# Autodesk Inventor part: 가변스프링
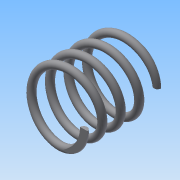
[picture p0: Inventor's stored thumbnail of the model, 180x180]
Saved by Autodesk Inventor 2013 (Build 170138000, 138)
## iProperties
Created: 2017-07
Part Number: 가변스프링
Material: 일반
Document SubType Name: Modeling
Designer: Administrator
Density: 1 g/cm^3
Author: Administrator
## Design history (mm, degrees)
sketch "스케치1"
  geometry: L1 (8.5, 0)-(0, 0); L2 (0, 0)-(0, 20.5); L3 (0, 20.5)-(8.5, 20.5); C1 r 1 at (8.5, 0)
  constraints: 6 end point, 1 centre point, 1 horizontal, 1 horizontal alignment, 1 parallel, 1 perpendicular
  dimensions: "d0" = 2 diameter of C1; "d1" = 8.5 distance of L1.start L1.end; "d2" = 8.5 distance of L2.end L3.end; "d3" = 20.5 distance of L1.end L2.end (derived)
feature "코일2" sketch "스케치1" pitch "d17" = 10; turns "d19" = 4; dims "d18" = 20.5 (= d3), "d20" = 0, angle "d21" = 90 deg, angle "d22" = 90 deg, "d23" = 0, "d24" = 0
sketch "스케치3"
  geometry: L1 (0, 15)-(20.5, 15); L2 (20.5, 15)-(20.5, -15); L3 (20.5, -15)-(0, -15); L4 (0, -15)-(0, 15); 2 further points
  constraints: 8 end point, 2 parallel, 1 coincident, 1 horizontal, 1 midpoint, 1 perpendicular
  dimensions: "d25" = 30 distance of L1.end L2.end; "d27" = 20.5 distance of L1.start L1.end (derived)
extrude "돌출2" sketch "스케치3" stored distance "d28" = 30; taper "d29" = 0 deg
node "솔리드2"
